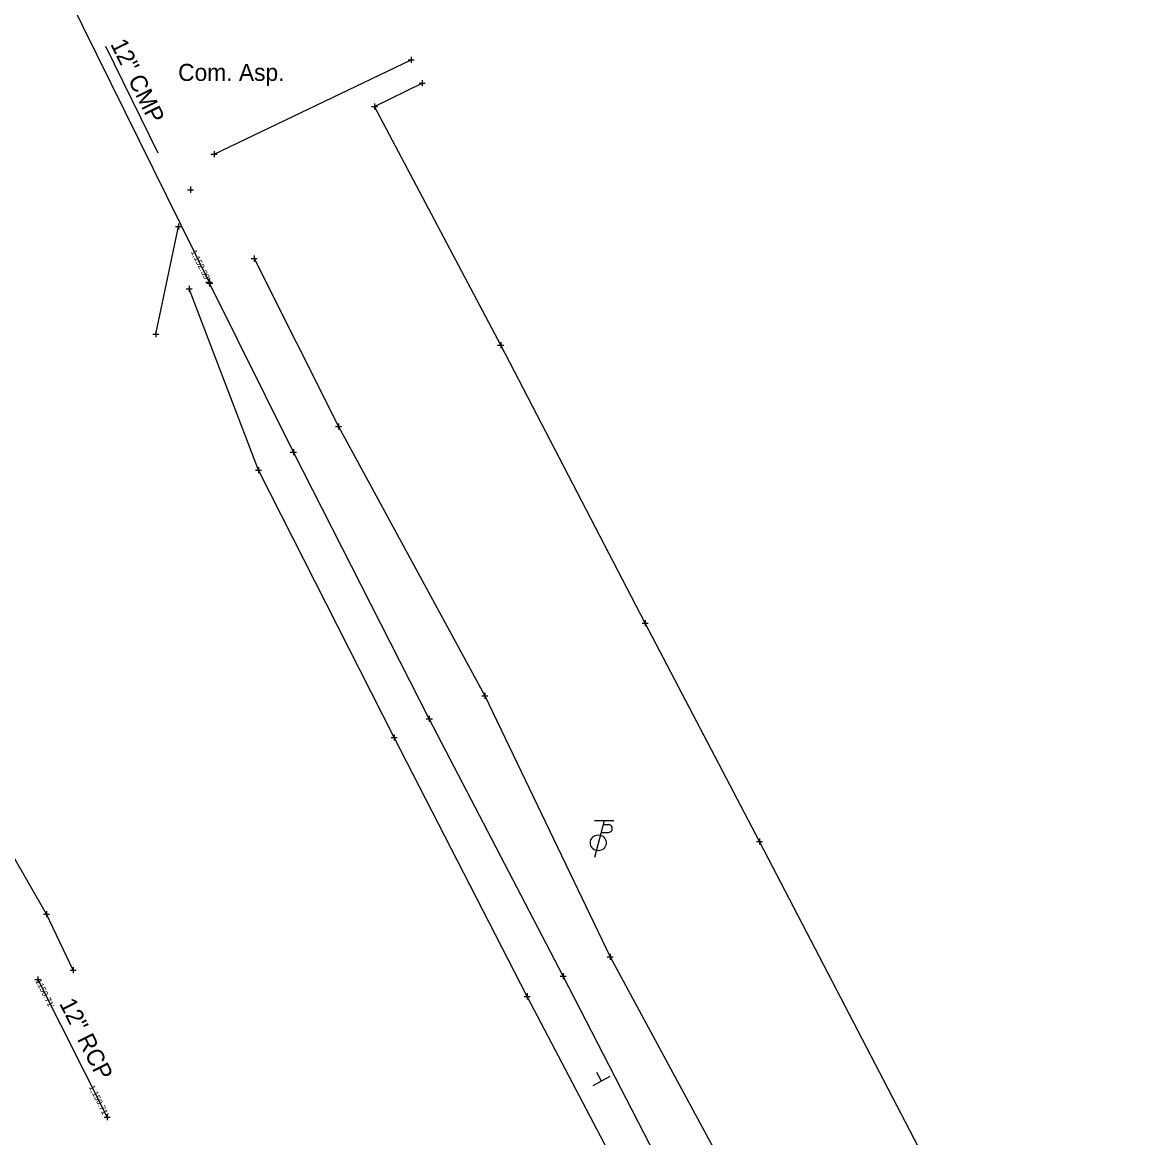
# Model space of a CAD drawing. Extents: x 2298098 to 2302860, y 557788 to 564251.
# Drawn here: x 2299294.7 to 2299476.3, y 561934.3 to 562117.7 of the extents above; entities that cross this region are included whole.
import ezdxf

# ---------------------------------------------------------------- set-up
doc = ezdxf.new("R2010")
doc.units = 0
for name, color, linetype in [('DR_X_Ditch', 7, 'Continuous'), ('DR_X_Elev_Flow', 7, 'Continuous'), ('DR_X_Storm_Sewer', 7, 'Continuous'), ('DR_X_Text', 7, 'Continuous'), ('PV_X_Driveway', 7, 'Continuous'), ('PV_X_Text', 7, 'Continuous'), ('RD_X_Fence', 7, 'Continuous'), ('SC_Scratch1', 7, 'Continuous'), ('SN_X_Public', 7, 'Continuous'), ('SV_X_Break_Lines', 7, 'Continuous'), ('SV_X_Shot_Marker', 7, 'Continuous'), ('UT_X_Misc_Cells', 7, 'Continuous')]:
    doc.layers.add(name, color=color, linetype=linetype)

msp = doc.modelspace()

# ---------------------------------------------------------------- linework, layer by layer
at = {"layer": 'DR_X_Ditch'}
msp.add_lwpolyline([(2299428.32, 561888.87), (2299407.2, 561914.87), (2299383.55, 561960.87), (2299361.56, 562003.18), (2299339.22, 562047), (2299325.46, 562074.75)], dxfattribs=at)
at = {"layer": 'DR_X_Elev_Flow'}
for p, q in [((2299324.86, 562074.96), (2299325.86, 562074.96)), ((2299325.36, 562075.46), (2299325.36, 562074.46)), ((2299325.36, 562074.96), (2299325.36, 562074.96)), ((2299297.25, 561960.79), (2299297.25, 561959.79)), ((2299296.75, 561960.29), (2299297.75, 561960.29)), ((2299297.25, 561960.29), (2299297.25, 561960.29)), ((2299308.14, 561937.68), (2299309.14, 561937.68)), ((2299308.64, 561938.18), (2299308.64, 561937.18)), ((2299308.64, 561937.68), (2299308.64, 561937.68))]:
    msp.add_line(p, q, dxfattribs=at)
at = {"layer": 'DR_X_Storm_Sewer'}
for p, q in [((2299294.87, 562136.78), (2299325.36, 562074.96)), ((2299297.25, 561960.29), (2299308.64, 561937.68))]:
    msp.add_line(p, q, dxfattribs=at)
at = {"layer": 'DR_X_Text'}
msp.add_line((2299317.02, 562096.16), (2299308.38, 562113.67), dxfattribs=at)
at = {"layer": 'PV_X_Driveway'}
for p, q in [((2299326.18, 562095.99), (2299358.58, 562111.5)), ((2299316.63, 562066.38), (2299320.37, 562084.08))]:
    msp.add_line(p, q, dxfattribs=at)
at = {"layer": 'RD_X_Fence'}
msp.add_lwpolyline([(2299470.73, 561878.32), (2299444.74, 561927.36), (2299415.8, 561982.99), (2299397.04, 562018.9), (2299373.29, 562064.6), (2299352.56, 562103.81), (2299360.38, 562107.66)], dxfattribs=at)
at = {"layer": 'SN_X_Public'}
for p, q in [((2299391.24, 561944.35), (2299388.42, 561942.83)), ((2299389.83, 561943.59), (2299389.07, 561945))]:
    msp.add_line(p, q, dxfattribs=at)
at = {"layer": 'SV_X_Break_Lines'}
for points in [[(2299303.03, 561961.85), (2299298.64, 561971.05), (2299273.44, 562014.95), (2299250.22, 562059.41), (2299226.48, 562104.95), (2299203.42, 562147.89), (2299181.06, 562192.17), (2299158.67, 562235.79), (2299135.94, 562280.91), (2299112.63, 562324.69), (2299090.03, 562369.28), (2299067.09, 562413.5), (2299042.93, 562453.45)], [(2299332.77, 562078.83), (2299346.63, 562051.21), (2299370.67, 562006.96), (2299391.28, 561964.02), (2299415.88, 561918.53), (2299450.24, 561871.53), (2299473.43, 561868.32)], [(2299476.32, 561861.23), (2299443.65, 561862.53), (2299401.2, 561912.66), (2299377.65, 561957.54), (2299355.79, 562000.1), (2299333.47, 562044.05), (2299322.09, 562073.82)]]:
    msp.add_lwpolyline(points, dxfattribs=at)
at = {"layer": 'SV_X_Shot_Marker'}
for p, q in [((2299358.08, 562111.5), (2299359.08, 562111.5)), ((2299358.58, 562112), (2299358.58, 562111)), ((2299358.58, 562111.5), (2299358.58, 562111.5)), ((2299359.88, 562107.66), (2299360.88, 562107.66)), ((2299360.38, 562108.16), (2299360.38, 562107.16)), ((2299360.38, 562107.66), (2299360.38, 562107.66)), ((2299352.06, 562103.81), (2299353.06, 562103.81)), ((2299352.56, 562104.31), (2299352.56, 562103.31)), ((2299352.56, 562103.81), (2299352.56, 562103.81)), ((2299326.18, 562096.49), (2299326.18, 562095.49)), ((2299325.68, 562095.99), (2299326.68, 562095.99)), ((2299326.18, 562095.99), (2299326.18, 562095.99)), ((2299321.8, 562090.14), (2299322.8, 562090.14)), ((2299322.3, 562090.64), (2299322.3, 562089.64)), ((2299322.3, 562090.14), (2299322.3, 562090.14)), ((2299319.87, 562084.08), (2299320.87, 562084.08)), ((2299320.37, 562084.58), (2299320.37, 562083.58)), ((2299320.37, 562084.08), (2299320.37, 562084.08)), ((2299332.27, 562078.83), (2299333.27, 562078.83)), ((2299332.77, 562079.33), (2299332.77, 562078.33)), ((2299332.77, 562078.83), (2299332.77, 562078.83)), ((2299322.09, 562074.32), (2299322.09, 562073.32)), ((2299324.96, 562074.75), (2299325.96, 562074.75)), ((2299325.46, 562075.25), (2299325.46, 562074.25)), ((2299325.46, 562074.75), (2299325.46, 562074.75)), ((2299321.59, 562073.82), (2299322.59, 562073.82)), ((2299322.09, 562073.82), (2299322.09, 562073.82)), ((2299316.13, 562066.38), (2299317.13, 562066.38)), ((2299316.63, 562066.88), (2299316.63, 562065.88)), ((2299316.63, 562066.38), (2299316.63, 562066.38)), ((2299373.29, 562065.1), (2299373.29, 562064.1)), ((2299372.79, 562064.6), (2299373.79, 562064.6)), ((2299373.29, 562064.6), (2299373.29, 562064.6)), ((2299346.13, 562051.21), (2299347.13, 562051.21)), ((2299346.63, 562051.71), (2299346.63, 562050.71)), ((2299346.63, 562051.21), (2299346.63, 562051.21)), ((2299338.72, 562047), (2299339.72, 562047)), ((2299339.22, 562047.5), (2299339.22, 562046.5)), ((2299339.22, 562047), (2299339.22, 562047)), ((2299332.97, 562044.05), (2299333.97, 562044.05)), ((2299333.47, 562044.55), (2299333.47, 562043.55)), ((2299333.47, 562044.05), (2299333.47, 562044.05)), ((2299397.04, 562019.4), (2299397.04, 562018.4)), ((2299396.54, 562018.9), (2299397.54, 562018.9)), ((2299397.04, 562018.9), (2299397.04, 562018.9)), ((2299370.17, 562006.96), (2299371.17, 562006.96)), ((2299370.67, 562007.46), (2299370.67, 562006.46)), ((2299370.67, 562006.96), (2299370.67, 562006.96)), ((2299361.06, 562003.18), (2299362.06, 562003.18)), ((2299361.56, 562003.68), (2299361.56, 562002.68)), ((2299361.56, 562003.18), (2299361.56, 562003.18)), ((2299355.29, 562000.1), (2299356.29, 562000.1)), ((2299355.79, 562000.6), (2299355.79, 561999.6)), ((2299355.79, 562000.1), (2299355.79, 562000.1)), ((2299415.3, 561982.99), (2299416.3, 561982.99)), ((2299415.8, 561983.49), (2299415.8, 561982.49)), ((2299415.8, 561982.99), (2299415.8, 561982.99)), ((2299298.64, 561971.55), (2299298.64, 561970.55)), ((2299298.14, 561971.05), (2299299.14, 561971.05)), ((2299298.64, 561971.05), (2299298.64, 561971.05)), ((2299391.28, 561964.52), (2299391.28, 561963.52)), ((2299390.78, 561964.02), (2299391.78, 561964.02)), ((2299391.28, 561964.02), (2299391.28, 561964.02)), ((2299302.53, 561961.85), (2299303.53, 561961.85)), ((2299303.03, 561962.35), (2299303.03, 561961.35)), ((2299303.03, 561961.85), (2299303.03, 561961.85)), ((2299383.05, 561960.87), (2299384.05, 561960.87)), ((2299383.55, 561961.37), (2299383.55, 561960.37)), ((2299383.55, 561960.87), (2299383.55, 561960.87)), ((2299377.15, 561957.54), (2299378.15, 561957.54)), ((2299377.65, 561958.04), (2299377.65, 561957.04)), ((2299377.65, 561957.54), (2299377.65, 561957.54))]:
    msp.add_line(p, q, dxfattribs=at)
at = {"layer": 'UT_X_Misc_Cells'}
for p, q in [((2299390.29, 561986.38), (2299388.68, 561980.38)), ((2299391.89, 561986.38), (2299388.69, 561986.38)), ((2299389.78, 561984.5), (2299390.98, 561984.5)), ((2299390.13, 561985.78), (2299390.98, 561985.78))]:
    msp.add_line(p, q, dxfattribs=at)
msp.add_circle((2299389.32, 561982.78), 1.3, dxfattribs=at)
msp.add_arc((2299390.99, 561985.14), 0.638, 268.8767, 91.1233, dxfattribs=at)

# ---------------------------------------------------------------- texts
at = {"layer": 'DR_X_Text'}
for s, rotation, p in [('12" CMP', 296.2561, (2299309.1, 562114.09)), ('12" RCP', 296.7411, (2299300.7, 561956.37))]:
    msp.add_text(s, height=2.8, rotation=rotation, dxfattribs=at).set_placement(p)
at = {"layer": 'PV_X_Text'}
msp.add_text('Com. Asp.', height=2.8, dxfattribs=at).set_placement((2299320.28, 562108.02))
at = {"layer": 'SC_Scratch1'}
for s, rotation, p in [("1,152.39'", 296.2561, (2299322.34, 562079.94)), ("1150.71'", 296.7411, (2299296.8, 561960.07)), ("1,150.71'", 296.7411, (2299305.58, 561942.63))]:
    msp.add_text(s, height=1, rotation=rotation, dxfattribs=at).set_placement(p)

doc.saveas('drawing.dxf')
